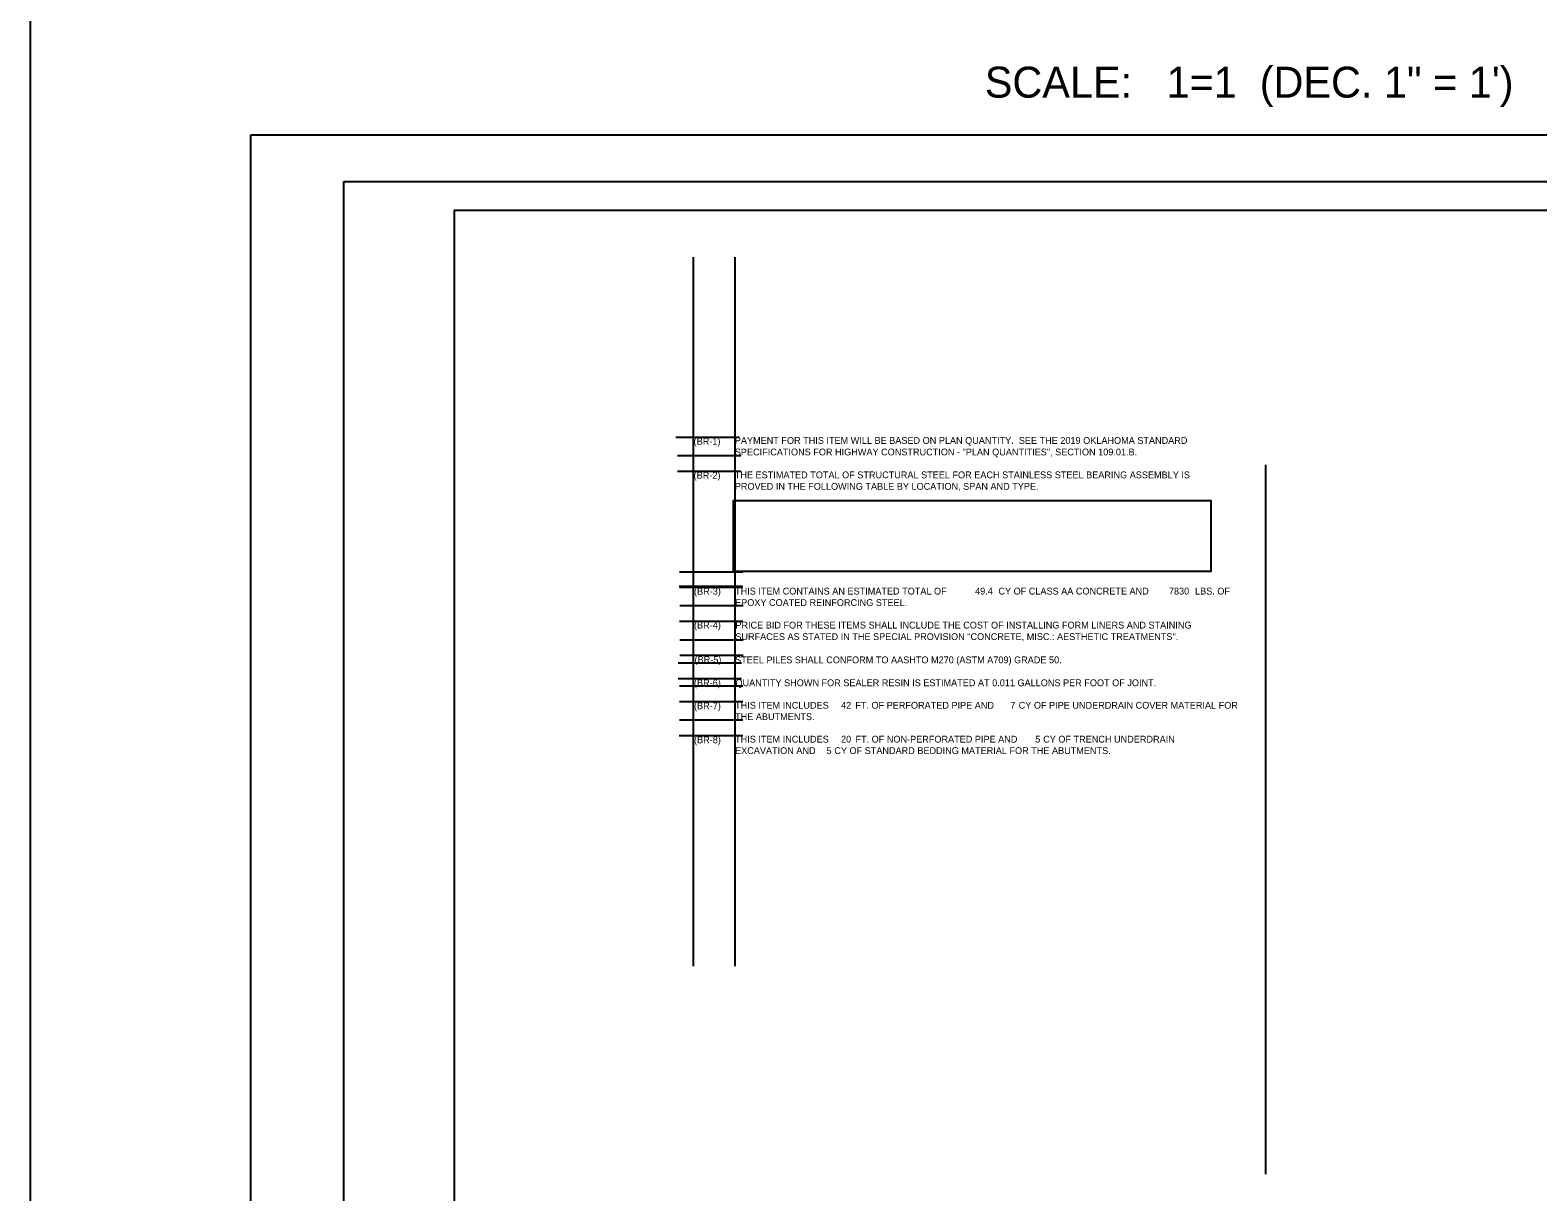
# Model space of a CAD drawing. Extents: x 12306 to 12361.5, y 578.9 to 640.4.
# Drawn here: x 12312.48 to 12339.03, y 589.85 to 610.31 of the extents above; entities that cross this region are included whole.
import ezdxf

# ---------------------------------------------------------------- set-up
doc = ezdxf.new("R2010")
doc.units = 0
for name, color, linetype in [('S', 7, 'Continuous'), ('SHT_Plot_Shape_Full', 7, 'Continuous'), ('SHT_Plot_Shape_Half', 7, 'Continuous'), ('SHT_Sheet_Border', 7, 'Continuous'), ('T', 7, 'Continuous')]:
    doc.layers.add(name, color=color, linetype=linetype)

msp = doc.modelspace()

# ---------------------------------------------------------------- linework, layer by layer
at = {"layer": 'Defpoints'}
for p, q in [((12324.161, 593.823), (12324.161, 606.315)), ((12324.886, 606.315), (12324.886, 593.823)), ((12324.963, 603.138), (12323.847, 603.138)), ((12324.993, 602.814), (12323.878, 602.814)), ((12324.993, 602.54), (12323.878, 602.54)), ((12334.24, 590.163), (12334.24, 602.655)), ((12325.027, 600.766), (12323.912, 600.766)), ((12325.023, 600.511), (12323.907, 600.511)), ((12325.027, 600.492), (12323.912, 600.492)), ((12325.027, 600.492), (12323.912, 600.492)), ((12325.036, 600.169), (12323.92, 600.169)), ((12325.027, 599.894), (12323.912, 599.894)), ((12325.036, 599.569), (12323.92, 599.569)), ((12325.002, 599.16), (12323.886, 599.16)), ((12325.036, 599.295), (12323.92, 599.295)), ((12325.002, 598.886), (12323.886, 598.886)), ((12325.027, 598.756), (12323.911, 598.756)), ((12325.027, 598.482), (12323.911, 598.482)), ((12325.029, 598.157), (12323.913, 598.157)), ((12325.024, 597.883), (12323.908, 597.883)), ((12325.027, 597.883), (12323.911, 597.883))]:
    msp.add_line(p, q, dxfattribs=at)
at = {"layer": 'S'}
msp.add_lwpolyline([(12355.912, 640.357), (12312.476, 640.357), (12312.476, 578.901), (12355.912, 578.901)], close=True, dxfattribs=at)
at = {"layer": 'SHT_Plot_Shape_Full'}
msp.add_lwpolyline([(12316.36, 608.469), (12352.36, 608.469), (12352.36, 584.469), (12316.36, 584.469)], close=True, dxfattribs=at)
at = {"layer": 'SHT_Plot_Shape_Half'}
msp.add_lwpolyline([(12317.998, 607.644), (12351.998, 607.644), (12351.998, 585.644), (12317.998, 585.644)], close=True, dxfattribs=at)
at = {"layer": 'SHT_Sheet_Border'}
msp.add_lwpolyline([(12351.448, 586.144), (12319.948, 586.144), (12319.948, 607.144), (12351.448, 607.144)], close=True, dxfattribs=at)
at = {"layer": 'T'}
msp.add_lwpolyline([(12324.857, 600.782), (12333.274, 600.782), (12333.274, 602.019), (12324.857, 602.019)], close=True, dxfattribs=at)

# ---------------------------------------------------------------- texts
at = {"layer": 'S'}
msp.add_text('SCALE:   1=1  (DEC. 1" = 1\')', height=0.54513, dxfattribs=at).set_placement((12329.289, 609.124))
at = {"layer": 'T'}
for s, p in [('(BR-1)', (12324.161, 603.01)), ('PAYMENT FOR THIS ITEM WILL BE BASED ON PLAN QUANTITY.  SEE THE 2019 OKLAHOMA STANDARD ', (12324.886, 603.025)), ('SPECIFICATIONS FOR HIGHWAY CONSTRUCTION - "PLAN QUANTITIES", SECTION 109.01.B.', (12324.886, 602.822)), ('(BR-2)', (12324.161, 602.411)), ('THE ESTIMATED TOTAL OF STRUCTURAL STEEL FOR EACH STAINLESS STEEL BEARING ASSEMBLY IS ', (12324.886, 602.419)), ('PROVED IN THE FOLLOWING TABLE BY LOCATION, SPAN AND TYPE.', (12324.886, 602.216)), ('(BR-3)', (12324.168, 600.369)), ('THIS ITEM CONTAINS AN ESTIMATED TOTAL OF ', (12324.891, 600.371)), ('49.4', (12329.118, 600.371)), (' CY OF CLASS AA CONCRETE AND ', (12329.484, 600.371)), ('7830', (12332.531, 600.371)), (' LBS. OF ', (12332.947, 600.371)), ('EPOXY COATED REINFORCING STEEL.', (12324.891, 600.169)), ('(BR-4)', (12324.168, 599.772)), ('PRICE BID FOR THESE ITEMS SHALL INCLUDE THE COST OF INSTALLING FORM LINERS AND STAINING ', (12324.896, 599.772)), ('SURFACES AS STATED IN THE SPECIAL PROVISION "CONCRETE, MISC.: AESTHETIC TREATMENTS".', (12324.896, 599.569)), ('(BR-5)', (12324.177, 599.165)), ('STEEL PILES SHALL CONFORM TO AASHTO M270 (ASTM A709) GRADE 50.', (12324.891, 599.16)), ('(BR-6)', (12324.167, 598.754)), ('QUANTITY SHOWN FOR SEALER RESIN IS ESTIMATED AT 0.011 GALLONS PER FOOT OF JOINT.', (12324.898, 598.756)), ('(BR-7)', (12324.168, 598.35)), ('THIS ITEM INCLUDES ', (12324.891, 598.36)), ('THE ABUTMENTS. ', (12324.891, 598.159)), ('42', (12326.757, 598.36)), (' FT. OF PERFORATED PIPE AND ', (12326.963, 598.36)), ('7', (12329.738, 598.36)), (' CY OF PIPE UNDERDRAIN COVER MATERIAL FOR ', (12329.841, 598.36)), ('(BR-8)', (12324.168, 597.751)), ('THIS ITEM INCLUDES ', (12324.891, 597.763)), ('20', (12326.757, 597.763)), (' FT. OF NON-PERFORATED PIPE AND ', (12326.966, 597.763)), ('5', (12330.177, 597.763)), (' CY OF TRENCH UNDERDRAIN ', (12330.272, 597.763)), ('EXCAVATION AND ', (12324.891, 597.561)), ('5', (12326.498, 597.561)), (' CY OF STANDARD BEDDING MATERIAL FOR THE ABUTMENTS.  ', (12326.594, 597.561))]:
    msp.add_text(s, height=0.12, dxfattribs=at).set_placement(p)

doc.saveas('drawing.dxf')
